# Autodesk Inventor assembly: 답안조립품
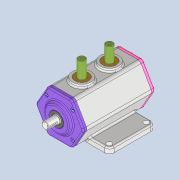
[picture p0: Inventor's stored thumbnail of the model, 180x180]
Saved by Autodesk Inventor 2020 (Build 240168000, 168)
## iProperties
Created: 2021-06
Part Number: 답안조립품
Document SubType Name: Assembly
Designer: MIRAE
Author: MIRAE
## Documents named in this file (11)
- C:\Users\MIRAE\Desktop\710606V1031\답안조립품.iam
- C:\Users\MIRAE\Desktop\710606V1031\본체.ipt
- C:\Users\MIRAE\Desktop\710606V1031\뒷커버.ipt
- C:\Users\MIRAE\Desktop\710606V1031\베어링 6203.ipt
- C:\Users\MIRAE\Desktop\710606V1031\베어링 6302.ipt
- C:\Users\MIRAE\Desktop\710606V1031\볼트 M4.ipt
- C:\Users\MIRAE\Desktop\710606V1031\부시.ipt
- C:\Users\MIRAE\Desktop\710606V1031\슬라이더.ipt
- C:\Users\MIRAE\Desktop\710606V1031\앞커버.ipt
- C:\Users\MIRAE\Desktop\710606V1031\오일실.ipt
- C:\Users\MIRAE\Desktop\710606V1031\편심축.ipt
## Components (10 placed, 3 different names)
1. 7-베어링 6203:1
2. 8-오일실:1
3. 9-M4-소켓머리:2 — 각도:2
4. 9-M4-소켓머리:3
5. 9-M4-소켓머리:4
6. 9-M4-소켓머리:5
7. 9-M4-소켓머리:1 — 각도:1
8. 9-M4-소켓머리:6
9. 9-M4-소켓머리:7
10. 9-M4-소켓머리:8
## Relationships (2: Angle 2)
- 각도:1 [Angle]: 9-M4-소켓머리:1
- 각도:2 [Angle]: 9-M4-소켓머리:2
